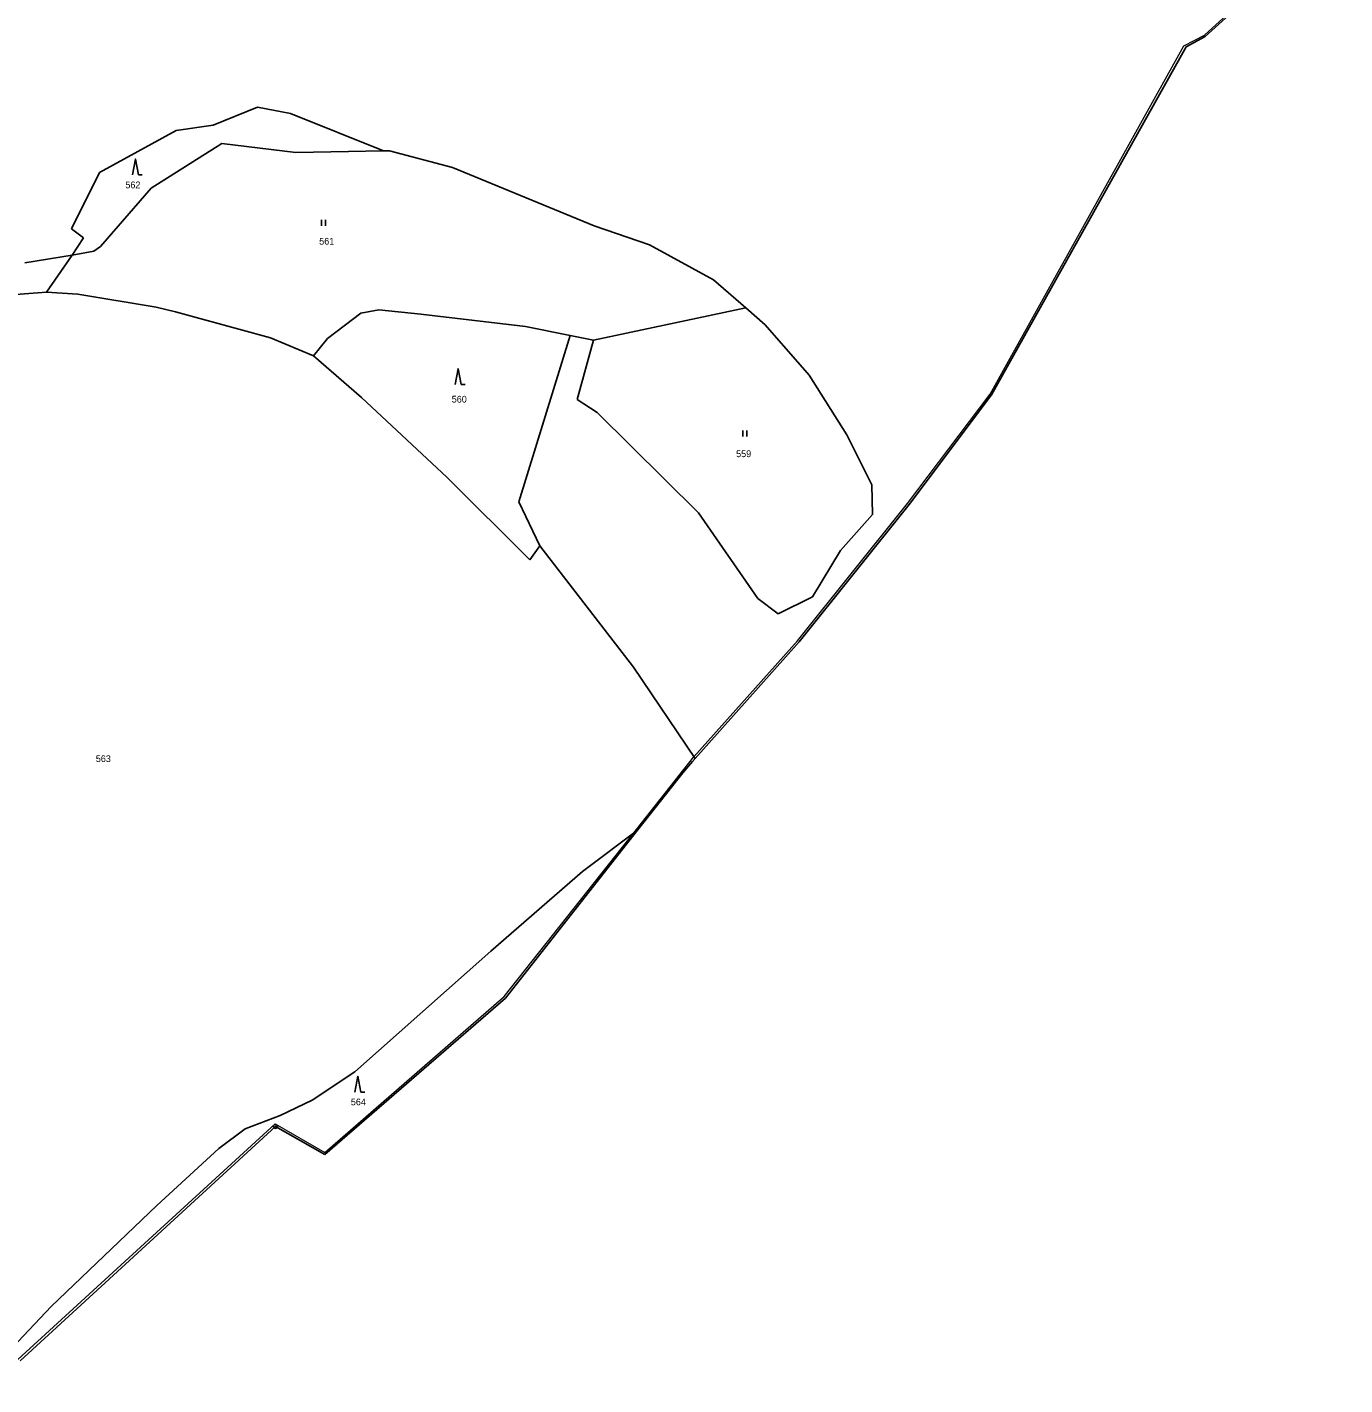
# Model space of a CAD drawing. Extents: x -653193 to -651624, y -1092017 to -1090260.
# Drawn here: x -652409.3 to -652077, y -1091806.2 to -1091464 of the extents above; entities that cross this region are included whole.
import ezdxf
from ezdxf.enums import TextEntityAlignment as Align

# ---------------------------------------------------------------- set-up
doc = ezdxf.new("R2010")
doc.units = 0
doc.header["$LTSCALE"] = 0.68
for name, color, linetype, lineweight in [('1', 7, 'Continuous', 25), ('3', 7, 'Continuous', 25), ('4', 7, 'Continuous', 13), ('8', 7, 'Continuous', 25)]:
    doc.layers.add(name, color=color, linetype=linetype, lineweight=lineweight)
doc.layers.add('2', color=7, linetype='Continuous')

msp = doc.modelspace()

# ---------------------------------------------------------------- linework, layer by layer
at = {"layer": '1'}
for p, q in [((-652112.2, -1091466.36), (-652105.44, -1091460.25)), ((-652116.98, -1091468.96), (-652112.2, -1091466.36)), ((-652166.08, -1091556.72), (-652116.98, -1091468.96)), ((-652362.37, -1091488.68), (-652351.2, -1091484.19)), ((-652351.2, -1091484.19), (-652342.83, -1091485.74)), ((-652371.68, -1091490.08), (-652362.37, -1091488.68)), ((-652342.83, -1091485.74), (-652319.44, -1091495.21)), ((-652391.03, -1091500.63), (-652371.68, -1091490.08)), ((-652360.18, -1091493.34), (-652378, -1091504.59)), ((-652341.52, -1091495.6), (-652360.18, -1091493.34)), ((-652319.44, -1091495.21), (-652341.52, -1091495.6)), ((-652319.44, -1091495.21), (-652317.9, -1091495.18)), ((-652317.9, -1091495.18), (-652302, -1091499.39)), ((-652398.11, -1091514.87), (-652391.03, -1091500.63)), ((-652302, -1091499.39), (-652266.32, -1091514.1)), ((-652378, -1091504.59), (-652390.73, -1091519.32)), ((-652395.08, -1091517.12), (-652398.11, -1091514.87)), ((-652266.32, -1091514.1), (-652252.32, -1091518.9)), ((-652397.91, -1091521.47), (-652395.08, -1091517.12)), ((-652390.73, -1091519.32), (-652392.47, -1091520.5)), ((-652252.32, -1091518.9), (-652236.17, -1091527.7)), ((-652409.8, -1091523.38), (-652397.91, -1091521.47)), ((-652404.4, -1091530.77), (-652397.91, -1091521.47)), ((-652392.47, -1091520.5), (-652397.91, -1091521.47)), ((-652236.17, -1091527.7), (-652228.06, -1091534.74)), ((-652404.4, -1091530.77), (-652414.4, -1091531.54)), ((-652396.49, -1091531.34), (-652404.4, -1091530.77)), ((-652376.69, -1091534.58), (-652396.49, -1091531.34)), ((-652371.84, -1091535.75), (-652376.69, -1091534.58)), ((-652347.88, -1091542.28), (-652371.84, -1091535.75)), ((-652333.55, -1091542.5), (-652325.16, -1091536.09)), ((-652325.16, -1091536.09), (-652320.62, -1091535.25)), ((-652320.62, -1091535.25), (-652310.02, -1091536.34)), ((-652310.02, -1091536.34), (-652283.56, -1091539.47)), ((-652266.44, -1091542.91), (-652228.06, -1091534.74)), ((-652228.06, -1091534.74), (-652223.14, -1091539.04)), ((-652283.56, -1091539.47), (-652272.34, -1091541.72)), ((-652223.14, -1091539.04), (-652212.08, -1091551.7)), ((-652337.05, -1091546.87), (-652347.88, -1091542.28)), ((-652337.05, -1091546.87), (-652333.55, -1091542.5)), ((-652272.34, -1091541.72), (-652285.27, -1091583.68)), ((-652266.44, -1091542.91), (-652272.34, -1091541.72)), ((-652270.61, -1091557.84), (-652266.44, -1091542.91)), ((-652324.91, -1091557.33), (-652337.05, -1091546.87)), ((-652212.08, -1091551.7), (-652202.59, -1091566.74)), ((-652303.37, -1091577.56), (-652324.91, -1091557.33)), ((-652186.89, -1091584.33), (-652166.08, -1091556.72)), ((-652265.56, -1091561.17), (-652270.61, -1091557.84)), ((-652239.94, -1091586.43), (-652265.56, -1091561.17)), ((-652202.59, -1091566.74), (-652196.3, -1091579.38)), ((-652282.48, -1091598.27), (-652303.37, -1091577.56)), ((-652196.3, -1091579.38), (-652196.08, -1091586.81)), ((-652285.27, -1091583.68), (-652280.02, -1091594.72)), ((-652214.64, -1091618.97), (-652186.89, -1091584.33)), ((-652225, -1091607.98), (-652239.94, -1091586.43)), ((-652196.08, -1091586.81), (-652204.15, -1091595.89)), ((-652280.02, -1091594.72), (-652282.48, -1091598.27)), ((-652280.02, -1091594.72), (-652256.33, -1091625.32)), ((-652204.15, -1091595.89), (-652211.27, -1091607.61)), ((-652219.9, -1091611.85), (-652225, -1091607.98)), ((-652211.27, -1091607.61), (-652219.9, -1091611.85)), ((-652240.79, -1091648.31), (-652214.64, -1091618.97)), ((-652256.33, -1091625.32), (-652240.79, -1091648.31)), ((-652243.94, -1091651.99), (-652241.49, -1091649.1)), ((-652240.79, -1091648.31), (-652241.49, -1091649.1)), ((-652255.32, -1091666.45), (-652243.94, -1091651.99)), ((-652288.61, -1091708.76), (-652255.32, -1091666.45)), ((-652255.32, -1091666.45), (-652269.22, -1091676.83)), ((-652269.22, -1091676.83), (-652292.36, -1091696.93)), ((-652292.36, -1091696.93), (-652326.64, -1091727.32)), ((-652334.21, -1091748.21), (-652288.61, -1091708.76)), ((-652326.64, -1091727.32), (-652337.36, -1091734.48)), ((-652337.36, -1091734.48), (-652345.44, -1091738.3)), ((-652345.44, -1091738.3), (-652354.28, -1091741.66)), ((-652411.02, -1091800.15), (-652346.65, -1091741.1)), ((-652354.28, -1091741.66), (-652360.92, -1091746.66)), ((-652346.65, -1091741.1), (-652334.21, -1091748.21)), ((-652360.92, -1091746.66), (-652376.54, -1091761.06)), ((-652376.54, -1091761.06), (-652403.23, -1091786.47)), ((-652403.23, -1091786.47), (-652412.95, -1091796.78))]:
    msp.add_line(p, q, dxfattribs=at)
at = {"layer": '3'}
for p, q in [((-652381.21, -1091501.26), (-652380.214, -1091501.26)), ((-652335.021, -1091514.06), (-652335.021, -1091512.56)), ((-652334.02, -1091514.06), (-652334.02, -1091512.56)), ((-652299.83, -1091554.12), (-652298.834, -1091554.12)), ((-652228.801, -1091567.17), (-652228.801, -1091565.67)), ((-652227.8, -1091567.17), (-652227.8, -1091565.67)), ((-652325.12, -1091732.44), (-652324.124, -1091732.44))]:
    msp.add_line(p, q, dxfattribs=at)
for points in [[(-652381.21, -1091501.26), (-652381.96, -1091497.26), (-652382.71, -1091501.26)], [(-652299.83, -1091554.12), (-652300.58, -1091550.12), (-652301.33, -1091554.12)], [(-652325.12, -1091732.44), (-652325.87, -1091728.44), (-652326.62, -1091732.44)]]:
    msp.add_lwpolyline(points, dxfattribs=at)
at = {"layer": '4'}
msp.add_lwpolyline([(-652418.64, -1091806.23), (-652346.74, -1091740.45), (-652334.23, -1091747.66), (-652288.98, -1091708.35), (-652255.65, -1091666.22), (-652241.19, -1091647.92), (-652215.03, -1091618.69), (-652187.29, -1091584.1), (-652166.47, -1091556.54), (-652117.59, -1091468.69), (-652112.38, -1091466.02), (-652077.01, -1091433.77)], dxfattribs=at)
at = {"layer": '8'}
for radius in [0.5, 0.0303]:
    msp.add_circle((-652346.65, -1091741.0999), radius, dxfattribs=at)

# ---------------------------------------------------------------- texts
at = {"layer": '2'}
for s, p in [('562', (-652382.599, -1091504.615)), ('561', (-652333.719, -1091518.825)), ('560', (-652300.299, -1091558.635)), ('559', (-652228.599, -1091572.385)), ('563', (-652390.049, -1091649.245)), ('564', (-652325.739, -1091735.775))]:
    msp.add_text(s, height=1.7, dxfattribs=at).set_placement(p, align=Align.CENTER)

doc.saveas('drawing.dxf')
